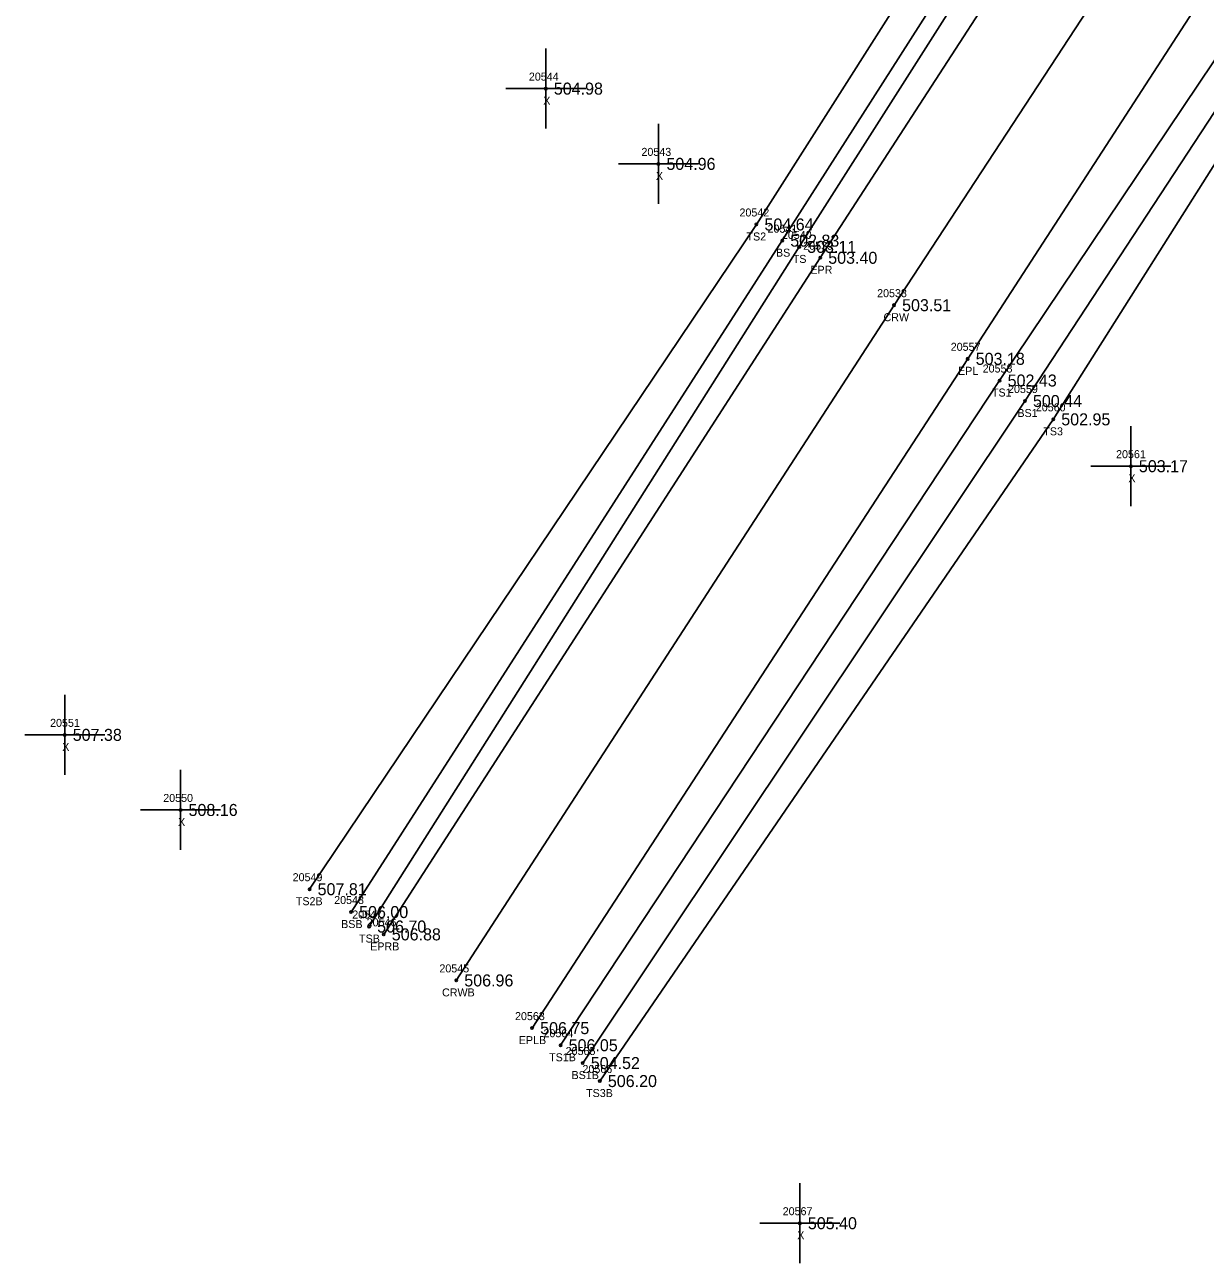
# Model space of a CAD drawing. Extents: x 1741010 to 1742139, y 749382 to 750625.
# Drawn here: x 1741109.9 to 1741257.4, y 749381.6 to 749536.3 of the extents above; entities that cross this region are included whole.
import ezdxf

# ---------------------------------------------------------------- set-up
doc = ezdxf.new("R2010")
doc.units = 0
for name, color, linetype in [('RD_DTM_BkLn1', 7, 'Continuous'), ('RD_DTM_BkLn2', 7, 'Continuous'), ('RD_DTM_BkLn_txCode', 7, 'Continuous'), ('RD_EX_Misc', 7, 'Continuous'), ('RD_EX_Misc_txCode', 7, 'Continuous'), ('RD_EX_Road', 7, 'Continuous'), ('RD_EX_Road_txCode', 7, 'Continuous'), ('RD_EX_TX_Misc_ELEV', 7, 'Continuous'), ('RD_EX_TX_Road_ELEV', 7, 'Continuous'), ('RD_HC_Survey_ELEV', 7, 'Continuous'), ('RD_HC_Survey_txCode', 7, 'Continuous'), ('RD_SMD_Locator', 7, 'Continuous')]:
    doc.layers.add(name, color=color, linetype=linetype)

msp = doc.modelspace()

# ---------------------------------------------------------------- linework, layer by layer
at = {"layer": 'RD_DTM_BkLn1'}
msp.add_lwpolyline([(1741583.42, 750045.09), (1741578.78, 750039.19), (1741548.6, 749999.46), (1741519.68, 749959.35), (1741491.7, 749918.15), (1741464.01, 749876.67), (1741436.51, 749835.23), (1741409.05, 749793.46), (1741381.95, 749752.07), (1741327.4, 749668.12), (1741273.18, 749584.75), (1741218.51, 749501.3), (1741163.8, 749416.96)], dxfattribs=at)
at = {"layer": 'RD_DTM_BkLn2'}
for points in [[(1741595, 750038.14), (1741592, 750028.61), (1741562.19, 749990.08), (1741531.32, 749949.92), (1741504.18, 749910.32), (1741476.42, 749868.74), (1741449.21, 749826.98), (1741421.85, 749784.9), (1741395.46, 749743.34), (1741340.74, 749659.13), (1741287.12, 749574.46), (1741231.7, 749491.89), (1741176.84, 749408.86)], [(1741599.45, 750031.16), (1741593.66, 750027.37), (1741564.55, 749987.86), (1741532.82, 749948.93), (1741506.71, 749908.62), (1741479.05, 749867.73), (1741451.41, 749825.96), (1741424.08, 749783.57), (1741397.6, 749742.18), (1741343.11, 749657.77), (1741289.87, 749573.19), (1741234.86, 749489.33), (1741179.61, 749406.64)], [(1741602.3, 750028.04), (1741596.22, 750024.37), (1741565.72, 749986.92), (1741536.13, 749947.45), (1741509.05, 749906.34), (1741480.78, 749866.4), (1741453.63, 749824.8), (1741427.39, 749781.55), (1741401.53, 749739.33), (1741346.85, 749655.57), (1741291.93, 749571.65), (1741238.4, 749487.04), (1741181.74, 749404.39)], [(1741250.94, 749581.46), (1741248.52, 749582.6), (1741243.75, 749578.1), (1741201.31, 749511.38), (1741145.47, 749428.35)], [(1741250.94, 749581.46), (1741251.75, 749579.72), (1741248.32, 749574.04), (1741206.65, 749508.58), (1741152.91, 749423.69)], [(1741250.59, 749580.63), (1741246.66, 749575.4), (1741204.53, 749509.36), (1741150.66, 749425.5)]]:
    msp.add_lwpolyline(points, dxfattribs=at)
at = {"layer": 'RD_EX_Misc'}
for p, q in [((1741174.99, 749523.35), (1741174.99, 749533.35)), ((1741169.99, 749528.35), (1741179.99, 749528.35)), ((1741189.06, 749513.95), (1741189.06, 749523.95)), ((1741184.06, 749518.95), (1741194.06, 749518.95)), ((1741248.1, 749476.19), (1741248.1, 749486.19)), ((1741243.1, 749481.19), (1741253.1, 749481.19)), ((1741114.87, 749442.63), (1741114.87, 749452.63)), ((1741109.87, 749447.63), (1741119.87, 749447.63)), ((1741129.34, 749433.25), (1741129.34, 749443.25)), ((1741124.34, 749438.25), (1741134.34, 749438.25)), ((1741206.73, 749381.63), (1741206.73, 749391.63)), ((1741201.73, 749386.63), (1741211.73, 749386.63))]:
    msp.add_line(p, q, dxfattribs=at)
at = {"layer": 'RD_EX_Road'}
for points in [[(1741574.14, 750053.03), (1741573.09, 750050.35), (1741570.35, 750045.84), (1741539.87, 750005.43), (1741510.87, 749966.19), (1741482.97, 749924.75), (1741454.76, 749883.01), (1741427.14, 749841.37), (1741399.6, 749799.14), (1741372.83, 749758.13), (1741317.93, 749673.6), (1741267.39, 749595.97), (1741263.6, 749591.05), (1741254, 749576.22), (1741209.28, 749507.22), (1741154.74, 749422.71)], [(1741592.65, 750037.91), (1741590.39, 750035.78), (1741587.68, 750032.32), (1741557.76, 749993.29), (1741528.74, 749952.66), (1741501.16, 749912.21), (1741473.5, 749870.53), (1741446.05, 749829.26), (1741418.1, 749787.13), (1741391.18, 749745.79), (1741336.54, 749661.65), (1741282.05, 749578.36), (1741227.71, 749494.6), (1741173.28, 749411)]]:
    msp.add_lwpolyline(points, dxfattribs=at)
at = {"layer": 'RD_SMD_Locator'}
for centre in [(1741174.99, 749528.35), (1741189.06, 749518.95), (1741201.31, 749511.38), (1741204.53, 749509.36), (1741206.65, 749508.58), (1741209.28, 749507.22), (1741218.51, 749501.3), (1741227.71, 749494.6), (1741231.7, 749491.89), (1741234.86, 749489.33), (1741238.4, 749487.04), (1741248.1, 749481.19), (1741114.87, 749447.63), (1741129.34, 749438.25), (1741145.47, 749428.35), (1741150.66, 749425.5), (1741152.91, 749423.69), (1741154.74, 749422.71), (1741163.8, 749416.96), (1741173.28, 749411), (1741176.84, 749408.86), (1741179.61, 749406.64), (1741181.74, 749404.39), (1741206.73, 749386.63)]:
    msp.add_circle(centre, 0.15, dxfattribs=at)

# ---------------------------------------------------------------- texts
at = {"layer": 'RD_DTM_BkLn_txCode'}
for s, p in [('20542', (1741199.19, 749512.38)), ('TS2', (1741200.07, 749509.38)), ('20541', (1741202.7, 749510.36)), ('20540', (1741204.49, 749509.58)), ('BS', (1741203.75, 749507.36)), ('TS', (1741205.85, 749506.58)), ('20558', (1741229.58, 749492.89)), ('20559', (1741232.75, 749490.33)), ('TS1', (1741230.74, 749489.89)), ('BS1', (1741233.92, 749487.33)), ('20560', (1741236.22, 749488.04)), ('TS3', (1741237.16, 749485.04)), ('20549', (1741143.35, 749429.35)), ('TS2B', (1741143.75, 749426.35)), ('20548', (1741148.54, 749426.5)), ('20547', (1741150.8, 749424.69)), ('BSB', (1741149.41, 749423.5)), ('TSB', (1741151.65, 749421.69)), ('20564', (1741174.7, 749409.86)), ('TS1B', (1741175.4, 749406.86)), ('20565', (1741177.47, 749407.64)), ('20566', (1741179.57, 749405.39)), ('BS1B', (1741178.2, 749404.64)), ('TS3B', (1741180.02, 749402.39))]:
    msp.add_text(s, height=1, dxfattribs=at).set_placement(p)
at = {"layer": 'RD_EX_Misc_txCode'}
for s, p in [('20544', (1741172.87, 749529.35)), ('X', (1741174.67, 749526.35)), ('20543', (1741186.94, 749519.95)), ('X', (1741188.75, 749516.95)), ('20561', (1741246.25, 749482.19)), ('X', (1741247.79, 749479.19)), ('20551', (1741113.04, 749448.63)), ('X', (1741114.56, 749445.63)), ('20550', (1741127.18, 749439.25)), ('X', (1741129.03, 749436.25)), ('20567', (1741204.59, 749387.63)), ('X', (1741206.41, 749384.63))]:
    msp.add_text(s, height=1, dxfattribs=at).set_placement(p)
at = {"layer": 'RD_EX_Road_txCode'}
for s, p in [('20539', (1741207.16, 749508.22)), ('EPR', (1741208.05, 749505.22)), ('20557', (1741225.59, 749495.6)), ('EPL', (1741226.5, 749492.6)), ('20546', (1741152.6, 749423.71)), ('EPRB', (1741153.04, 749420.71)), ('20563', (1741171.14, 749412)), ('EPLB', (1741171.61, 749409))]:
    msp.add_text(s, height=1, dxfattribs=at).set_placement(p)
at = {"layer": 'RD_EX_TX_Misc_ELEV'}
for s, p in [('504.98', (1741175.99, 749527.6)), ('504.96', (1741190.06, 749518.2)), ('504.64', (1741202.31, 749510.63)), ('502.83', (1741205.53, 749508.61)), ('503.11', (1741207.65, 749507.83)), ('502.43', (1741232.7, 749491.14)), ('500.44', (1741235.86, 749488.58)), ('502.95', (1741239.4, 749486.29)), ('503.17', (1741249.1, 749480.44)), ('507.38', (1741115.87, 749446.88)), ('508.16', (1741130.34, 749437.5)), ('507.81', (1741146.47, 749427.6)), ('506.00', (1741151.66, 749424.75)), ('506.70', (1741153.91, 749422.94)), ('506.05', (1741177.84, 749408.11)), ('504.52', (1741180.61, 749405.89)), ('506.20', (1741182.74, 749403.64)), ('505.40', (1741207.73, 749385.88))]:
    msp.add_text(s, height=1.5, dxfattribs=at).set_placement(p)
at = {"layer": 'RD_EX_TX_Road_ELEV'}
for s, p in [('503.40', (1741210.28, 749506.47)), ('503.18', (1741228.71, 749493.85)), ('506.88', (1741155.74, 749421.96)), ('506.75', (1741174.28, 749410.25))]:
    msp.add_text(s, height=1.5, dxfattribs=at).set_placement(p)
at = {"layer": 'RD_HC_Survey_ELEV'}
for s, p in [('503.51', (1741219.51, 749500.55)), ('506.96', (1741164.8, 749416.21))]:
    msp.add_text(s, height=1.5, dxfattribs=at).set_placement(p)
at = {"layer": 'RD_HC_Survey_txCode'}
for s, p in [('20538', (1741216.39, 749502.3)), ('CRW', (1741217.19, 749499.3)), ('20545', (1741161.69, 749417.96)), ('CRWB', (1741162.02, 749414.96))]:
    msp.add_text(s, height=1, dxfattribs=at).set_placement(p)

doc.saveas('drawing.dxf')
